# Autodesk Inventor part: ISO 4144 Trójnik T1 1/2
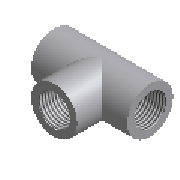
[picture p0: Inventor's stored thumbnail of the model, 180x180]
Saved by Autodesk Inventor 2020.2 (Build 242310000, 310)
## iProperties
Manager: www.cadconsulting.pl
Company: Fabian Stasiak CAD Consulting
NAME: PIPING: ISO 4144 Tee B1
DATA: <meta><inlinegroups number="1" deflen="5.6"></inlinegroups><connections number="3"></connections><angles><a>3.14159265358979</a><a>1.5707963267949</a></angles><
IsCustomPart: 0
Created: 2014-02
Part Number: ISO 4144 Trójnik T1 1/2
Material: Stal nierdzewna
Description: Rurociągi - Elementy ze stali nierdzewnej gwintowane zgodnie z ISO 7-1
Document SubType Name: Modeling
Standard: ISO 4144
Designer: F.Stasiak
Standard Revision: Second edition 2003-03-15
Standards Organization: ISO
Language: pl-PL
Size Designation: 1/2
Categories: <MemberInstance><Categories><Category DisplayName="Rury cienko- i grubościenne" InternalName="4347fa0f-2144-441d-94cd-e3e15c92b736" Mnemonic="TUBEANDPIPE"><Cate
Density: 1 g/cm^3
Appearance: Częściowo polerowana
Catalog Web Link: www.expertbooks.pl
Author: F.Stasiak
Subject: Zbiór ćwiczeń. Autodesk Inventor 2020. Kurs Professional
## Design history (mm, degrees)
sketch "Sketch1"
  geometry: L1 (0, 0)-(56, 0); L2 (56, 0)-(56, 9.316); L3 (28, 0)-(28, 13.5); L4 (0, 0)-(0, 9.316); L5 (0, 9.316)-(12.7, 8.919); L6 (56, 9.316)-(43.3, 8.919); L7 (0, 9.316)-(0, 13.5); L8 (56, 9.316)-(56, 13.5); L9 (12.7, 8.919)-(43.3, 8.919); L10 (0, 13.5)-(56, 13.5); L11 (12.7, 8.919)-(12.7, 0); L12 (43.3, 8.919)-(43.3, 0)
  constraints: 24 end point, 4 perpendicular, 2 midpoint, 2 parallel, 2 point on line, 2 symmetric about line, 1 horizontal, 3 other
  dimensions: "d0" = 18.631 diameter of L4.end L1 (= MD); "d1" = 12.7 horizontal distance of L4.end L5.end (= L); "d2" = 28 distance between parallel lines of L3 L4 (= a); "d3" = 1.78991 deg angle of L1 L5; "d10" = 27 diameter of L10 L1 (= d)
revolve "Revolution1" sketch "Sketch1" stored, may be unused: angle "d8" = 90 deg
workplane "Work Plane1"
sketch "Sketch2"
  geometry: L1 (0, 0)-(56, 0) reference; L2 (28, 0)-(28, 13.5) reference; C1 r 13.5 at (28, 0); C2 r 9.316 at (28, 0)
  constraints: 2 centre point, 1 coincident, 1 concentric, 1 point on line
  dimensions: "d5" = 27 diameter of C1 (= d); "d7" = 18.631 diameter of C2 (= MD)
extrude "Extrusion1" join sketch "Sketch2" taper "d6" = 0 deg; stored distance "d11" = 10
extrude "Extrusion2" cut sketch "Sketch2" taper "d9" = -1.78991 deg; stored distance "d17" = 6.35 (= 0.5 x L)
workplane "Work Plane2"
sketch "Sketch3"
  geometry: L1 (56, 0)-(0, 0) reference; L2 (28, 0)-(28, 28); L3 (28, 28)-(15.3, 28); L4 (15.3, 28)-(15.3, 15.3); L5 (15.3, 15.3)-(28, 15.3)
  constraints: 8 end point, 4 perpendicular, 1 midpoint, 1 point on line
  dimensions: "d42" = 28 distance of L2.start L2.end (= a); "d43" = 12.7 distance of L2.end L3.end (= L); "d44" = 12.7 distance of L3.end L4.end (= L)
workpoint "Work Point2"
workpoint "Work Point3"
workpoint "Work Point4"
workaxis "Work Axis2"
workpoint "Work Point5"
workaxis "Work Axis3"
workaxis "Work Axis4"
workpoint "Work Point6"
workaxis "Work Axis5"
workpoint "Work Point7"
body "Solid1"
feature "Gwint1" dims "d23" = 10, "d24" = 0
feature "Gwint2" dims "d25" = 10, "d26" = 0
feature "Gwint3" dims "d12" = 12.7 (= L), "d13" = 0
other parameters: "a" = 28 [user parameter; used in 3 equation terms], "d" = 27 [user parameter; used in 2 equation terms], "MD" = 18.631 [user parameter; used in 2 equation terms], "L" = 12.7 [user parameter; used in 5 equation terms], "d4" = 28 (= a), "Size_Designation" = 5 [user parameter]
